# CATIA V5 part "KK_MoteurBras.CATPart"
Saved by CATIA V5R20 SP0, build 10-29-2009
Part number: moteur bras
Bounding box of the stored display mesh (mm): x -113 to 113, y -72.5 to 72.5, z -100 to 240
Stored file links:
  G:\Khaled_CFAO_2011\ST2M\ST2M_GR2\tcorbin\Khaled\CAD_ThinkMOTION\KK_MoteurBras.CATPart
  F:\Thinkmotionperso\assemblage robot\ass_skl_robot.CATProduct
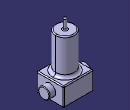
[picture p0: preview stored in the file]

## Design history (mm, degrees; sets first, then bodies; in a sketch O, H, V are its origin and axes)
External parameters (linked from other documents)
  `External.longueur moteur` = 190 mm
  `External.epaisseur avbrasbras` = 50 mm
  `External.epaisseur soc_espacechape` = 160 mm
  `External.diametre perçage chape_soc` = 60 mm
  `External.hauteur soc` = 100 mm
Set1
  Boundary1: Boundary face of Hole1
  Extract1: ExtractElem edge of Boundary1
  Extract2: ExtractElem edge of Boundary1
Body1 (main body)
  Sketch1 on xy-plane, origin (0, 0, 0), H (1, 0, 0), V (0, 1, 0)
    circle A1 centre (0, 0) radius 50
  Pad1: profile Sketch1, direction (0, 0, 1), length 190 {= `External.longueur moteur`}
  Sketch2 on end face of Pad1, origin (0, 0, 190), H (1, 0, 0), V (0, 1, 0)
    circle A1 centre (0, 0) radius 8.544
  Pad2: profile Sketch2, direction (0, 0, 1), length 50 {= `External.epaisseur avbrasbras`}
  Sketch3 on start face of Pad1, origin (0, 0, 0), H (1, 0, 0), V (0, -1, 0)
    line L1 (80, 72.5) -> (80, -72.5)
    line L2 (80, -72.5) -> (-80, -72.5)
    line L3 (-80, -72.5) -> (-80, 72.5)
    line L4 (-80, 72.5) -> (80, 72.5)
    length L4 = 160 {= `External.epaisseur soc_espacechape`}
    length L1 = 145
    vertical: L1 V, L3 V
    horizontal: L2 H, L4 H
    equidistance: L1 L3 O, L2 L4 O
  Pad3: profile Sketch3, direction (0, 0, -1), length 100 {= `External.hauteur soc`}
  Sketch4 on face of Pad3 from Sketch3.L1, origin (80, 10.9113, -60.8938), H (0, 1, 0), V (0, 0, 1)
    point P1 (-10.9113, 10.8938)
    reference projected line E1 (61.5887, 60.8938) -> (61.5887, -39.1062) from edge [face of Pad3 from Sketch3.L1 | face of Pad3 from Sketch3.L2]
    reference projected line E2 (61.5887, 60.8938) -> (-83.4113, 60.8938) from edge [start face of Pad3 | face of Pad3 from Sketch3.L1]
    distance P1 E1 = 72.5
    distance P1 E2 = 50
  Hole1: placed by Sketch4, at (80, 0, -50) direction (-1, 0, 0), diameter 60 {= `External.diametre perçage chape_soc`}, through (limit type 3)
  Fillet1: radius 5, on face of Pad3 from Sketch3.L4
  Fillet2: radius 5, on edge [start face of Pad3 | face of Pad3 from Sketch3.L3]; edge [face of Pad3 from Sketch3.L2 | face of Pad3 from Sketch3.L3]; edge [face of Pad3 from Sketch3.L3 | end face of Pad3]
  Fillet3: radius 5, on edge [start face of Pad3 | face of Pad3 from Sketch3.L2]; edge [face of Pad3 from Sketch3.L1 | face of Pad3 from Sketch3.L2]; edge [face of Pad3 from Sketch3.L2 | end face of Pad3]
  Fillet4: radius 5, on edge [start face of Pad3 | face of Pad3 from Sketch3.L1]; edge [face of Pad3 from Sketch3.L1 | end face of Pad3]
  FaceFillet1: Radius 15, Face1 face of Pad1 from Sketch1.A1, Face2 start face of Pad3, ConicRatio 0.5
  Fillet5: radius 5, on end face of Pad1
  Pad4: profile Extract1, length 33
  Pad5: profile Extract2, length 33
  Fillet6: radius 3, on end face of Pad4
  Fillet7: radius 3, on edge [face of Pad5 | end face of Pad5]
